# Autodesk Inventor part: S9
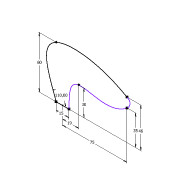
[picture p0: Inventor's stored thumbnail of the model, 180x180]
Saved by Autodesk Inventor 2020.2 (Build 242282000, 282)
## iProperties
Created: 2013-12
Part Number: S9
Material: Ogólny
Document SubType Name: Modeling
Designer: F.Stasiak
Density: 1 g/cm^3
Appearance: Domyślna
Manager: www.cadconsulting.pl
Company: Fabian Stasiak CAD Consulting
Author: F.Stasiak
Subject: Zbiór ćwiczeń. Autodesk Inventor 2020. Kurs podstawowy
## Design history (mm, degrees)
sketch "Szkic1"
  geometry: L1 (7.5, 0)-(-7.5, 0); L2 (-0.807, -18.39)-(-14.193, 18.39); L3 (7.5, -11.85)-(7.5, 11.85); A1 r 538.588 centre (-513.607, -184.208) between (-2.361, -14.783) and (-13.066, 14.628); A2 r 506.851 centre (-499.351, 0) between (7.411, -9.478) and (7.411, 9.478); 6 further points
  constraints: 6 end point, 5 midpoint, 2 centre point, 2 point on circle, 2 vertical, 2 vertical alignment, 1 coincident, 1 horizontal, 11 other
  dimensions: "d13" = 15 distance of L1.start L1.end; "d16" = 110 deg angle of L1 L2; "d17" = 15 dimension on L2.start L2.end; "d22" = 60 distance from line of point (-7.5, 60) L1; "d23" = 30 vertical distance of point (19, 30) point (0, 0); "d24" = 35 distance from line of point (75, 35) L1; "d26" = 19 horizontal distance of point (19, 30) point (0, 0); "d27" = 75 horizontal distance of point (75, 35) point (0, 0); "d28" = 46 distance from line of point (75, 46) L1
